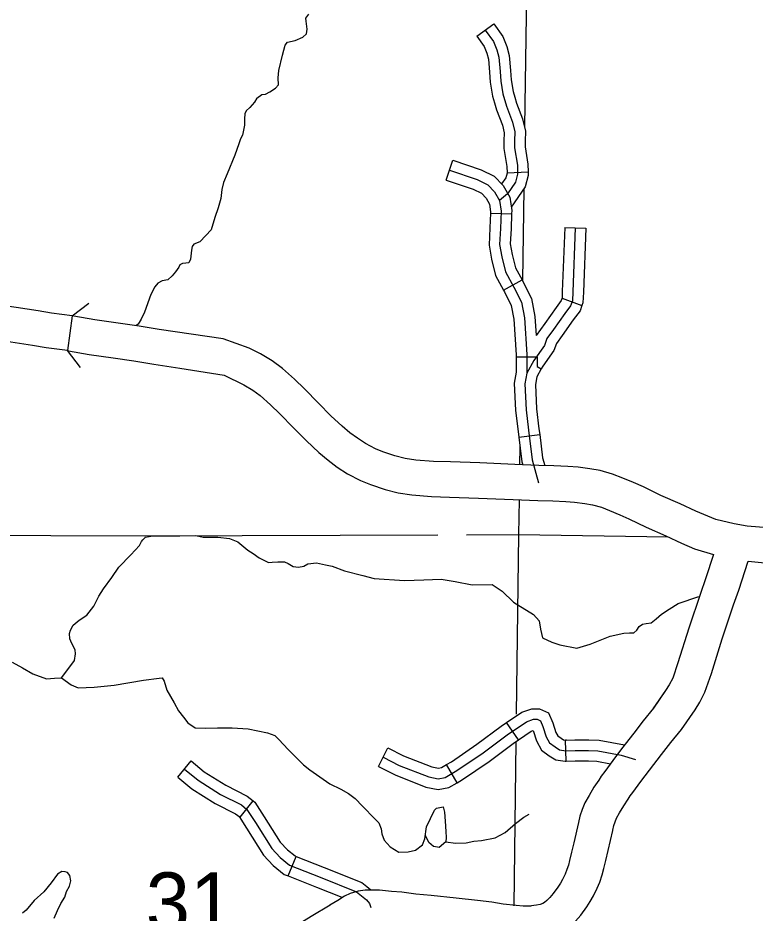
# Model space of a CAD drawing. Extents: x 813775 to 1157140, y 1757555 to 1979907.
# Drawn here: x 925607 to 936106, y 1817730 to 1830487 of the extents above; entities that cross this region are included whole.
import ezdxf

# ---------------------------------------------------------------- set-up
doc = ezdxf.new("R2010")
doc.units = 0
for name, color, linetype in [('Level 10', 7, 'Continuous'), ('Level 32', 7, 'Continuous'), ('Level 35', 7, 'Continuous'), ('Level 37', 7, 'Continuous'), ('Level 45', 7, 'Continuous'), ('Level 5', 7, 'Continuous')]:
    doc.layers.add(name, color=color, linetype=linetype)

msp = doc.modelspace()

# ---------------------------------------------------------------- linework, layer by layer
at = {"layer": 'Level 10'}
for points in [[(933545, 1827496), (933510, 1826585), (933505, 1826456), (933479, 1826385)], [(926379, 1826241), (926083, 1826279), (925893, 1826312), (925581, 1826359), (925340, 1826395)], [(933479, 1826385), (933394, 1826273), (933234, 1826046), (933141, 1825917), (933106, 1825819), (932955, 1825606), (932853, 1825424), (932826, 1825273), (932844, 1824904), (932879, 1824610), (932933, 1824188), (933020, 1823860)], [(926379, 1826241), (926314, 1825745)], [(928532, 1825912), (927620, 1826046), (927334, 1826096), (927035, 1826137), (926702, 1826186), (926402, 1826238), (926379, 1826241)], [(926314, 1825745), (926009, 1825785), (925814, 1825818), (925507, 1825864), (925266, 1825900)], [(930555, 1824422), (930441, 1824496), (930335, 1824575), (930226, 1824667), (930064, 1824818), (929887, 1824998), (929687, 1825201), (929545, 1825337), (929375, 1825489), (929229, 1825601), (929063, 1825698), (928898, 1825779), (928532, 1825912)], [(926314, 1825745), (926327, 1825744), (926623, 1825692), (926964, 1825642), (927257, 1825602), (927541, 1825552), (927915, 1825497), (928544, 1825396)], [(928544, 1825396), (928826, 1825257), (928951, 1825184), (929057, 1825104), (929205, 1824971), (929336, 1824845), (929531, 1824647), (929715, 1824460), (929894, 1824293), (930025, 1824183), (930155, 1824086), (930303, 1823990)], [(935548, 1823338), (935261, 1823458), (935038, 1823562), (934765, 1823681), (934517, 1823805), (934374, 1823865), (934223, 1823929), (934077, 1823987), (933899, 1824038), (933751, 1824063), (933584, 1824084), (933440, 1824095), (933241, 1824104), (933028, 1824110), (932683, 1824123), (932186, 1824145), (931770, 1824159), (931525, 1824167), (931273, 1824185), (931124, 1824209), (930977, 1824245), (930803, 1824305), (930699, 1824348), (930555, 1824422)], [(930303, 1823990), (930488, 1823894), (930627, 1823837), (930836, 1823765), (931024, 1823719), (931215, 1823688), (931499, 1823667), (931753, 1823659), (932167, 1823645), (932662, 1823624), (933012, 1823610), (933224, 1823604), (933409, 1823596), (933533, 1823586), (933679, 1823568), (933788, 1823550), (933916, 1823513), (934033, 1823467), (934179, 1823405), (934307, 1823350), (934553, 1823228), (934833, 1823105), (935059, 1823001), (935244, 1822923)], [(935808, 1823276), (935548, 1823338)], [(935991, 1823246), (935808, 1823276)], [(937109, 1823235), (936981, 1823222), (936888, 1823220), (936780, 1823213), (936693, 1823207), (936613, 1823206), (936554, 1823205), (936483, 1823206), (936410, 1823208), (936344, 1823216), (935991, 1823246)], [(935244, 1822923), (935512, 1822839)], [(935512, 1822839), (935400, 1822493), (935326, 1822283)], [(935799, 1822121), (935873, 1822333), (936007, 1822743)], [(936007, 1822743), (936294, 1822718), (936373, 1822709), (936470, 1822706), (936555, 1822705), (936622, 1822706), (936712, 1822708), (936811, 1822713), (936911, 1822720), (937013, 1822723), (937138, 1822736)], [(935326, 1822283), (935162, 1821790), (935007, 1821298), (934932, 1821076), (934883, 1820985), (934832, 1820901), (934651, 1820642)], [(935326, 1822283), (935162, 1821790), (935007, 1821298), (934932, 1821076), (934883, 1820985), (934832, 1820901), (934657, 1820650)], [(935056, 1820348), (935251, 1820628), (935317, 1820737), (935392, 1820876), (935483, 1821142), (935638, 1821637), (935799, 1822121)], [(934657, 1820650), (934511, 1820471), (934377, 1820292), (934205, 1820072), (934079, 1819903), (933964, 1819750), (933914, 1819682), (933878, 1819626), (933810, 1819524), (933742, 1819407), (933682, 1819300), (933644, 1819206), (933611, 1819112), (933591, 1819019)], [(934079, 1818911), (934093, 1818976), (934112, 1819031), (934133, 1819082), (934176, 1819159), (934235, 1819259), (934298, 1819353), (934327, 1819399), (934365, 1819450), (934480, 1819603), (934603, 1819769), (934774, 1819989), (934905, 1820163), (935056, 1820348)], [(933592, 1819022), (933523, 1818733), (933493, 1818597), (933463, 1818481), (933448, 1818411), (933426, 1818351), (933400, 1818287), (933362, 1818209), (933333, 1818158), (933296, 1818101), (933230, 1818010), (933181, 1817953), (933139, 1817910), (933106, 1817881), (933083, 1817868), (933043, 1817854), (932994, 1817844), (932884, 1817827)], [(932941, 1817330), (933082, 1817351), (933176, 1817371), (933291, 1817410), (933399, 1817472), (933484, 1817548), (933549, 1817614), (933623, 1817700), (933708, 1817818), (933759, 1817895), (933804, 1817974), (933858, 1818084), (933893, 1818172), (933930, 1818273), (933950, 1818367), (933979, 1818481), (934011, 1818621), (934078, 1818907)], [(932915, 1817830), (932804, 1817828), (932703, 1817837), (932518, 1817859), (932355, 1817884), (932153, 1817910), (931849, 1817944), (931492, 1817979), (931274, 1818000), (931075, 1818026), (930928, 1818039), (930758, 1818058), (930679, 1818059), (930630, 1818059), (930553, 1818056), (930451, 1818042), (930339, 1818007), (930259, 1817972), (930165, 1817910), (930051, 1817841)], [(930052, 1817842), (929781, 1817681), (929436, 1817469), (929084, 1817263), (928913, 1817149)]]:
    msp.add_lwpolyline(points, dxfattribs=at)
at = {"layer": 'Level 32'}
for p, q in [((931704, 1828176), (931799, 1828460)), ((932337, 1827704), (932637, 1827693)), ((933395, 1827502), (933695, 1827490)), ((932524, 1826607), (932787, 1826752)), ((933359, 1826494), (933640, 1826389)), ((932703, 1825658), (933003, 1825658)), ((933003, 1825518), (933060, 1825486)), ((932741, 1824510), (933038, 1824548)), ((932735, 1820198), (932567, 1820446)), ((933415, 1819894), (933405, 1820194)), ((930740, 1819817), (930875, 1820085)), ((927882, 1819666), (928072, 1819898)), ((931861, 1819587), (931711, 1819847)), ((928770, 1819095), (928955, 1819332)), ((929457, 1818260), (929568, 1818538))]:
    msp.add_line(p, q, dxfattribs=at)
for points in [[(931799, 1828460), (932204, 1828324), (932388, 1828232), (932516, 1828097), (932611, 1827932), (932639, 1827740), (932637, 1827693)], [(931752, 1828318), (932147, 1828185), (932298, 1828109), (932395, 1828007), (932466, 1827883), (932489, 1827732), (932480, 1827487), (932466, 1827256), (932497, 1827083), (932551, 1826869), (932671, 1826652), (932777, 1826438), (932822, 1826212), (932853, 1825692), (932853, 1825424)], [(931704, 1828176), (932089, 1828046), (932207, 1827987), (932274, 1827917), (932322, 1827833), (932338, 1827723), (932337, 1827704)], [(932337, 1827704), (932330, 1827494), (932316, 1827247), (932351, 1827051), (932410, 1826814), (932524, 1826607)], [(932637, 1827693), (932630, 1827480), (932617, 1827265), (932644, 1827114), (932692, 1826925), (932787, 1826752)], [(933395, 1827502), (933360, 1826590), (933356, 1826486), (933359, 1826494)], [(933695, 1827490), (933660, 1826579), (933654, 1826426), (933640, 1826389)], [(932787, 1826752), (932803, 1826721), (932920, 1826487), (932971, 1826231), (932987, 1825960)], [(932524, 1826607), (932538, 1826582), (932634, 1826389), (932672, 1826193), (932703, 1825687), (932703, 1825658)], [(933359, 1826494), (933346, 1826458), (933273, 1826361), (933112, 1826133), (932987, 1825960)], [(933640, 1826389), (933612, 1826312), (933516, 1826184), (933357, 1825959), (933275, 1825846), (933240, 1825749), (933082, 1825526), (933060, 1825486)], [(932703, 1825658), (932703, 1825437)], [(933003, 1825658), (933003, 1825518)], [(933060, 1825486), (932996, 1825373), (932977, 1825263), (932993, 1824916), (933028, 1824629), (933038, 1824548)], [(932703, 1825437), (932675, 1825282), (932694, 1824891), (932730, 1824592), (932741, 1824510)], [(932741, 1824510), (932785, 1824159), (932796, 1824119)], [(933038, 1824548), (933080, 1824217), (933109, 1824107)], [(932567, 1820446), (932782, 1820592), (932927, 1820643), (933033, 1820643), (933164, 1820584), (933226, 1820443), (933269, 1820302), (933294, 1820257), (933343, 1820221), (933375, 1820201), (933418, 1820194), (933404, 1820194)], [(930808, 1819951), (931038, 1819835), (931460, 1819671), (931593, 1819644), (931691, 1819662), (931860, 1819760), (932233, 1820013), (932575, 1820271), (932850, 1820457), (932952, 1820493), (933001, 1820493), (933050, 1820471), (933085, 1820391), (933130, 1820244), (933178, 1820155), (933258, 1820097), (933321, 1820057), (933409, 1820044), (933543, 1820048), (933733, 1820048), (933867, 1820044), (934200, 1819982), (934404, 1819921)], [(931711, 1819847), (931780, 1819887), (932145, 1820135), (932487, 1820393), (932567, 1820446)], [(932735, 1820198), (932918, 1820322), (932946, 1820332), (932991, 1820185), (933063, 1820053), (933174, 1819973), (933266, 1819914), (933401, 1819894), (933415, 1819894)], [(931861, 1819587), (931940, 1819632), (932320, 1819891), (932662, 1820149), (932735, 1820198)], [(933405, 1820194), (933540, 1820198), (933736, 1820198), (933883, 1820194), (934247, 1820126)], [(930875, 1820085), (931099, 1819972), (931503, 1819815), (931595, 1819797), (931639, 1819805), (931711, 1819847)], [(928072, 1819898), (928260, 1819744), (928566, 1819553), (928870, 1819398), (928955, 1819332)], [(933415, 1819894), (933545, 1819898), (933731, 1819898), (933850, 1819894), (934046, 1819858)], [(927977, 1819782), (928172, 1819622), (928492, 1819422), (928789, 1819271), (928869, 1819208), (928989, 1819022), (929224, 1818649), (929344, 1818520), (929477, 1818413), (929913, 1818240), (930428, 1818035), (930570, 1817920), (930614, 1817866), (930635, 1817809)], [(930740, 1819817), (930978, 1819698), (931418, 1819526), (931592, 1819491), (931744, 1819519), (931861, 1819587)], [(927882, 1819666), (928084, 1819500), (928418, 1819291), (928708, 1819143), (928770, 1819095)], [(928955, 1819332), (928981, 1819311), (929116, 1819102), (929344, 1818740), (929447, 1818630), (929554, 1818544), (929568, 1818538)], [(928757, 1819106), (928862, 1818941), (929105, 1818557), (929242, 1818409), (929401, 1818282), (929457, 1818260)], [(929568, 1818538), (929968, 1818379), (930504, 1818166), (930577, 1818107)], [(929457, 1818260), (929857, 1818100), (930222, 1817955)], [(930577, 1818107), (930635, 1818060)]]:
    msp.add_lwpolyline(points, dxfattribs=at)
at = {"layer": 'Level 35'}
for points in [[(929011, 1829345), (929079, 1829394), (929133, 1829402), (929196, 1829432), (929275, 1829484), (929318, 1829533), (929315, 1829631), (929324, 1829737), (929375, 1829954), (929413, 1830096), (929446, 1830139), (929555, 1830164), (929663, 1830213), (929718, 1830259), (929726, 1830324), (929710, 1830439), (929707, 1830484), (929748, 1830541)], [(929011, 1829345), (928975, 1829288), (928910, 1829209), (928858, 1829163), (928839, 1829119), (928834, 1829048), (928834, 1828959), (928820, 1828885), (928804, 1828815), (928776, 1828763), (928755, 1828692), (928695, 1828532)], [(928695, 1828532), (928589, 1828263), (928535, 1828143), (928513, 1828043), (928499, 1827915), (928461, 1827779), (928410, 1827643), (928358, 1827469), (928285, 1827387), (928198, 1827297), (928113, 1827262), (928089, 1827229), (928078, 1827175), (928067, 1827050), (928039, 1826998)], [(928039, 1826998), (927996, 1826994), (927950, 1826986), (927915, 1826967), (927899, 1826937), (927852, 1826866), (927803, 1826809), (927744, 1826755), (927662, 1826741), (927600, 1826709), (927556, 1826654), (927502, 1826545), (927409, 1826295), (927360, 1826194), (927320, 1826121), (927291, 1826102)], [(927337, 1822967), (927368, 1823024), (927384, 1823051), (927426, 1823089), (927527, 1823106), (927686, 1823106), (927914, 1823108), (928141, 1823110), (928244, 1823087), (928454, 1823085), (928619, 1823066), (928737, 1823020), (928823, 1822949), (928882, 1822904), (928955, 1822855), (929043, 1822794), (929176, 1822726), (929229, 1822729), (929310, 1822734), (929402, 1822736), (929454, 1822712), (929527, 1822669), (929602, 1822659), (929679, 1822674), (929734, 1822707), (929777, 1822711)], [(926228, 1821083), (926304, 1821184), (926413, 1821331), (926429, 1821423), (926424, 1821483), (926377, 1821570), (926345, 1821638), (926342, 1821712), (926358, 1821763), (926396, 1821831), (926478, 1821902), (926587, 1821975), (926690, 1822103), (926761, 1822245), (926826, 1822353), (926943, 1822510), (927043, 1822660), (927214, 1822834), (927337, 1822967)], [(929734, 1822707), (929861, 1822719), (929986, 1822691), (930081, 1822672), (930260, 1822607), (930521, 1822542), (930679, 1822496), (931114, 1822468), (931388, 1822479), (931635, 1822487), (931834, 1822455), (932076, 1822406), (932361, 1822411), (932505, 1822316), (932665, 1822161), (932951, 1821984), (933032, 1821897), (933049, 1821775), (933076, 1821652), (933212, 1821592), (933326, 1821554), (933565, 1821505), (933758, 1821563), (934043, 1821674), (934236, 1821718), (934318, 1821723), (934378, 1821726), (934421, 1821761), (934456, 1821816), (934500, 1821845), (934552, 1821859), (934625, 1821865), (934696, 1821922), (934774, 1821992), (934880, 1822060), (935011, 1822142), (935304, 1822243)], [(925525, 1821306), (925674, 1821227), (925821, 1821140), (926016, 1821070), (926128, 1821078), (926228, 1821083)], [(926228, 1821083), (926366, 1820985), (926464, 1820941), (926695, 1820950), (926978, 1820977), (927394, 1821050), (927619, 1821080)], [(927619, 1821080), (927660, 1821082), (927692, 1821035), (927728, 1820907), (927834, 1820728), (927893, 1820614), (927964, 1820524), (928026, 1820442), (928132, 1820369), (928279, 1820366), (928450, 1820369), (928657, 1820369), (928885, 1820358), (929162, 1820298), (929265, 1820260), (929325, 1820203), (929455, 1820062), (929673, 1819841), (929765, 1819773), (930048, 1819572)], [(930048, 1819572), (930207, 1819497), (930313, 1819432), (930409, 1819361), (930512, 1819252), (930691, 1819073), (930748, 1819018), (930778, 1818931), (930792, 1818858), (930822, 1818771), (930909, 1818676), (931034, 1818597), (931167, 1818605), (931267, 1818629)], [(931267, 1818629), (931368, 1818703), (931403, 1818790), (931425, 1818959), (931542, 1819195), (931569, 1819225), (931664, 1819244), (931683, 1819168), (931694, 1819038), (931702, 1818891), (931707, 1818806), (931699, 1818744), (931604, 1818665), (931582, 1818668), (931525, 1818679), (931460, 1818736), (931411, 1818834)], [(931699, 1818744), (931838, 1818728), (931990, 1818730), (932099, 1818755), (932210, 1818766), (932403, 1818804), (932547, 1818880), (932694, 1819005), (932814, 1819095), (932887, 1819141)], [(926123, 1817657), (926169, 1817769), (926216, 1817867), (926277, 1817955), (926299, 1818039), (926343, 1818112), (926360, 1818190), (926348, 1818264), (926314, 1818310), (926282, 1818318), (926230, 1818323), (926172, 1818283), (926081, 1818159), (925974, 1818031), (925837, 1817911), (925722, 1817774), (925673, 1817728)]]:
    msp.add_lwpolyline(points, dxfattribs=at)
at = {"layer": 'Level 37'}
for points in [[(926378, 1826241), (926615, 1826424)], [(926498, 1825507), (926315, 1825745)]]:
    msp.add_lwpolyline(points, dxfattribs=at)
at = {"layer": 'Level 45'}
for p, q in [((932142, 1830226), (932385, 1830402)), ((932574, 1828281), (932873, 1828292))]:
    msp.add_line(p, q, dxfattribs=at)
for points in [[(932385, 1830402), (932515, 1830221), (932571, 1830077), (932603, 1829951), (932623, 1829736), (932632, 1829605), (932661, 1829438), (932684, 1829356)], [(932142, 1830226), (932249, 1830077), (932285, 1829985), (932307, 1829900), (932324, 1829713), (932333, 1829570), (932368, 1829371), (932395, 1829275)], [(932263, 1830314), (932382, 1830149), (932428, 1830031), (932455, 1829926), (932473, 1829725), (932483, 1829587), (932515, 1829405), (932565, 1829227), (932651, 1829003), (932683, 1828861), (932679, 1828733), (932679, 1828637), (932720, 1828386), (932724, 1828258), (932693, 1828144), (932578, 1827979), (932466, 1827883)], [(932684, 1829356), (932707, 1829274), (932795, 1829047), (932834, 1828875), (932829, 1828730), (932829, 1828649), (932869, 1828401), (932873, 1828292)], [(932395, 1829275), (932422, 1829179), (932508, 1828959), (932533, 1828847), (932529, 1828736), (932529, 1828625), (932570, 1828371), (932574, 1828281)], [(932574, 1828281), (932574, 1828276), (932555, 1828209), (932494, 1828121)], [(932873, 1828292), (932875, 1828240), (932830, 1828079), (932631, 1827792)]]:
    msp.add_lwpolyline(points, dxfattribs=at)
at = {"layer": 'Level 5'}
for points in [[(932894, 1833694), (932823, 1828936)], [(932810, 1828050), (932791, 1826747)], [(932755, 1824375), (932752, 1824120)], [(932744, 1823620), (932737, 1823125)], [(923402, 1823119), (927410, 1823105), (931589, 1823121)], [(931997, 1823122), (932737, 1823125)], [(932737, 1823125), (932705, 1820566)], [(932737, 1823125), (934867, 1823090)], [(932700, 1820177), (932670, 1817835)]]:
    msp.add_lwpolyline(points, dxfattribs=at)

# ---------------------------------------------------------------- texts
msp.add_text('31', height=844.8, dxfattribs=at).set_placement((927428, 1817465))

doc.saveas('drawing.dxf')
